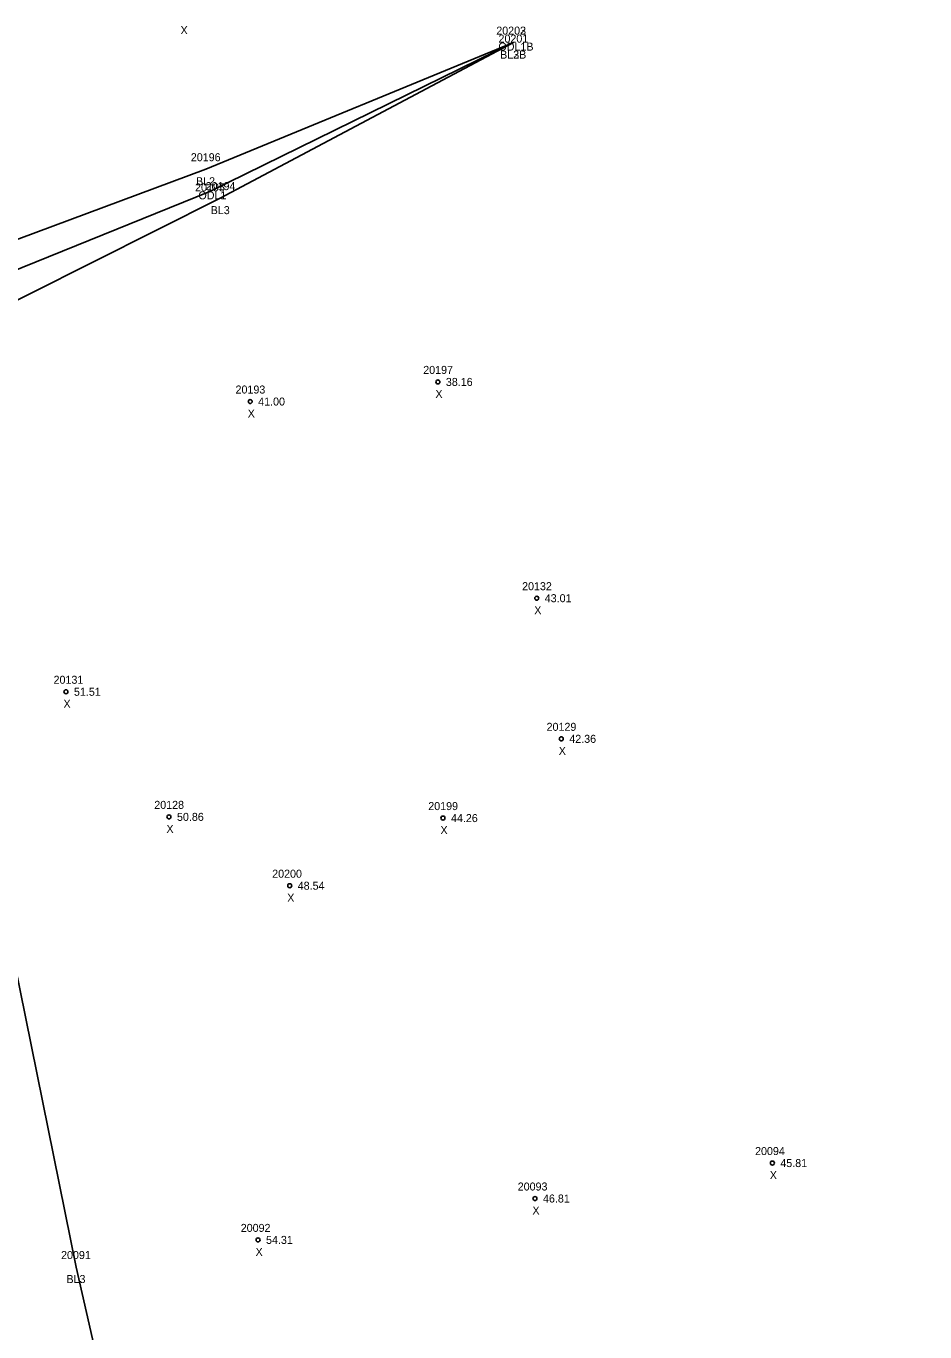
# Model space of a CAD drawing. Extents: x 2445178 to 2446260, y 791158 to 792318.
# Drawn here: x 2445783.8 to 2445896.2, y 791553.6 to 791716.7 of the extents above; entities that cross this region are included whole.
import ezdxf

# ---------------------------------------------------------------- set-up
doc = ezdxf.new("R2010")
doc.units = 0
for name, color, linetype in [('RD_DTM_BkLn1', 7, 'Continuous'), ('RD_EX_H2O', 7, 'Continuous'), ('RD_EX_H2O_txCode', 7, 'Continuous'), ('RD_Sketch8', 7, 'Continuous'), ('RD_SMD_Locator', 7, 'Continuous'), ('RD_SMD_Misc', 7, 'Continuous')]:
    doc.layers.add(name, color=color, linetype=linetype)

msp = doc.modelspace()

# ---------------------------------------------------------------- linework, layer by layer
at = {"layer": 'RD_DTM_BkLn1'}
for points in [[(2445882.78, 791184.78), (2445856.18, 791275.27), (2445839.04, 791329.43), (2445822.96, 791388.68), (2445805.7, 791444.65), (2445792.52, 791499.62), (2445777.56, 791559.78), (2445760.75, 791635.11), (2445757, 791668.89), (2445761.65, 791682.26), (2445806.3, 791698.85), (2445844.78, 791714.67)], [(2445896.2, 791187.37), (2445865.75, 791277.36), (2445863.45, 791286.42), (2445844.64, 791330.14), (2445831.75, 791389.47), (2445816.24, 791445.72), (2445804.21, 791499.93), (2445790.09, 791561.7), (2445779.57, 791613.54), (2445773.51, 791630.61), (2445764.7, 791668.39), (2445768.27, 791675.25), (2445808.12, 791695.24), (2445844.78, 791714.67)]]:
    msp.add_lwpolyline(points, dxfattribs=at)
at = {"layer": 'RD_EX_H2O'}
msp.add_lwpolyline([(2445885.63, 791185.34), (2445858.54, 791275.66), (2445841.27, 791329.71), (2445824.98, 791389.05), (2445808.2, 791445.07), (2445795.15, 791500.08), (2445780.4, 791559.92), (2445764.43, 791632.51), (2445759.72, 791668.56), (2445764.88, 791679.11), (2445806.8, 791696.09), (2445844.78, 791714.67)], dxfattribs=at)
at = {"layer": 'RD_SMD_Locator'}
for centre, radius in [((2445844.78, 791714.67), 0.001), ((2445844.78, 791714.67), 0.001), ((2445844.78, 791714.67), 0.001), ((2445806.3, 791698.85), 0.001), ((2445806.8, 791696.09), 0.001), ((2445808.12, 791695.24), 0.001), ((2445835.32, 791672.28), 0.25), ((2445811.86, 791669.83), 0.25), ((2445847.68, 791645.26), 0.25), ((2445788.83, 791633.57), 0.25), ((2445850.75, 791627.69), 0.25), ((2445801.71, 791617.94), 0.25), ((2445835.96, 791617.79), 0.25), ((2445816.8, 791609.34), 0.25), ((2445877.13, 791574.69), 0.25), ((2445847.46, 791570.26), 0.25), ((2445812.84, 791565.09), 0.25), ((2445790.09, 791561.7), 0.001)]:
    msp.add_circle(centre, radius, dxfattribs=at)

# ---------------------------------------------------------------- texts
at = {"layer": 'RD_EX_H2O_txCode'}
for s, p in [('20201', (2445842.9, 791714.67)), ('ODL1B', (2445842.89, 791713.67)), ('20195', (2445804.97, 791696.09)), ('ODL1', (2445805.39, 791695.09))]:
    msp.add_text(s, height=1, dxfattribs=at).set_placement(p)
at = {"layer": 'RD_Sketch8'}
for s, p in [('X', (2445803.15, 791715.73)), ('20197', (2445833.49, 791673.28)), ('38.16', (2445836.32, 791671.78)), ('20193', (2445810.03, 791670.83)), ('X', (2445835.01, 791670.28)), ('41.00', (2445812.86, 791669.33)), ('X', (2445811.55, 791667.83)), ('20132', (2445845.85, 791646.26)), ('43.01', (2445848.68, 791644.76)), ('X', (2445847.37, 791643.26)), ('20131', (2445787.28, 791634.57)), ('51.51', (2445789.83, 791633.07)), ('X', (2445788.52, 791631.57)), ('20129', (2445848.91, 791628.69)), ('42.36', (2445851.75, 791627.19)), ('X', (2445850.43, 791625.69)), ('20128', (2445799.87, 791618.94)), ('20199', (2445834.12, 791618.79)), ('50.86', (2445802.71, 791617.44)), ('44.26', (2445836.96, 791617.29)), ('X', (2445801.39, 791615.94)), ('X', (2445835.64, 791615.79)), ('20200', (2445814.61, 791610.34)), ('48.54', (2445817.8, 791608.84)), ('X', (2445816.49, 791607.34)), ('20094', (2445874.97, 791575.69)), ('45.81', (2445878.13, 791574.19)), ('X', (2445876.81, 791572.69)), ('20093', (2445845.3, 791571.26)), ('46.81', (2445848.46, 791569.76)), ('X', (2445847.14, 791568.26)), ('20092', (2445810.68, 791566.09)), ('54.31', (2445813.84, 791564.59)), ('X', (2445812.53, 791563.09))]:
    msp.add_text(s, height=1, dxfattribs=at).set_placement(p)
at = {"layer": 'RD_SMD_Misc'}
for s, p in [('20202', (2445842.62, 791715.67)), ('20203', (2445842.62, 791715.67)), ('BL2B', (2445843.1, 791712.67)), ('BL3B', (2445843.1, 791712.67)), ('20196', (2445804.44, 791699.85)), ('BL2', (2445805.09, 791696.85)), ('20194', (2445806.29, 791696.24)), ('BL3', (2445806.92, 791693.24)), ('20091', (2445788.22, 791562.7)), ('BL3', (2445788.89, 791559.7))]:
    msp.add_text(s, height=1, dxfattribs=at).set_placement(p)

doc.saveas('drawing.dxf')
